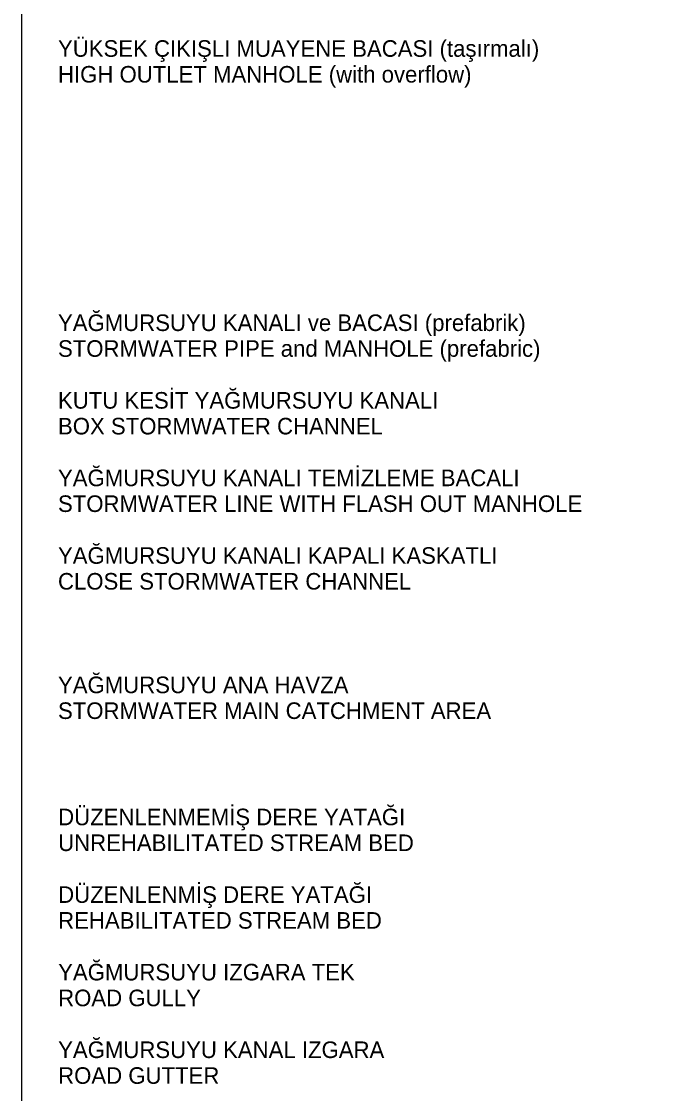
# Model space of a CAD drawing. Extents: x -10 to 1145, y -10 to 821.
# Drawn here: x 965 to 1043, y 552.8 to 683 of the extents above; entities that cross this region are included whole.
import ezdxf

# ---------------------------------------------------------------- set-up
doc = ezdxf.new("R2010")
doc.units = 0
doc.layers.add('Level 1', color=7, linetype='Continuous')
doc.layers.add('Level 52', color=7, linetype='Continuous')

msp = doc.modelspace()

# ---------------------------------------------------------------- linework, layer by layer
at = {"layer": 'Level 52'}
msp.add_lwpolyline([(965, 287), (1135, 287), (1135, 811), (965, 811)], close=True, dxfattribs=at)

# ---------------------------------------------------------------- texts
at = {"layer": 'Level 1'}
for s, height, p in [('YÜKSEK ÇIKIŞLI MUAYENE BACASI (taşırmalı)', 2.0119, (969.44, 678.67)), ('HIGH OUTLET MANHOLE (with overflow)', 2.0119, (969.44, 675.54)), ('YAĞMURSUYU KANALI ve BACASI (prefabrik)', 2.0119, (969.44, 645.39)), ('STORMWATER PIPE and MANHOLE (prefabric)', 2.0119, (969.44, 642.26)), ('KUTU KESİT YAĞMURSUYU KANALI', 2.0119, (969.44, 635.97)), ('BOX STORMWATER CHANNEL', 2.0119, (969.44, 632.84)), ('YAĞMURSUYU KANALI TEMİZLEME BACALI', 2.0119, (969.44, 626.56)), ('STORMWATER LINE WITH FLASH OUT MANHOLE', 2.0119, (969.44, 623.43)), ('YAĞMURSUYU KANALI KAPALI KASKATLI', 2.0119, (969.44, 617.14)), ('CLOSE STORMWATER CHANNEL', 2.0119, (969.44, 614.01)), ('YAĞMURSUYU ANA HAVZA', 2.0119, (969.44, 601.44)), ('STORMWATER MAIN CATCHMENT AREA', 2.0119, (969.44, 598.31)), ('DÜZENLENMEMİŞ DERE YATAĞI', 2.0119, (969.46, 585.41)), ('UNREHABILITATED STREAM BED', 2.0119, (969.46, 582.28)), ('DÜZENLENMİŞ DERE YATAĞI', 2.0119, (969.46, 575.99)), ('REHABILITATED STREAM BED', 2.0119, (969.46, 572.86)), ('YAĞMURSUYU IZGARA TEK', 2.0119, (969.46, 566.58)), ('ROAD GULLY', 2.012, (969.46, 563.45)), ('YAĞMURSUYU KANAL IZGARA', 2.0119, (969.46, 557.16)), ('ROAD GUTTER', 2.0119, (969.46, 554.03))]:
    msp.add_text(s, height=height, rotation=360, dxfattribs=at).set_placement(p)

doc.saveas('drawing.dxf')
